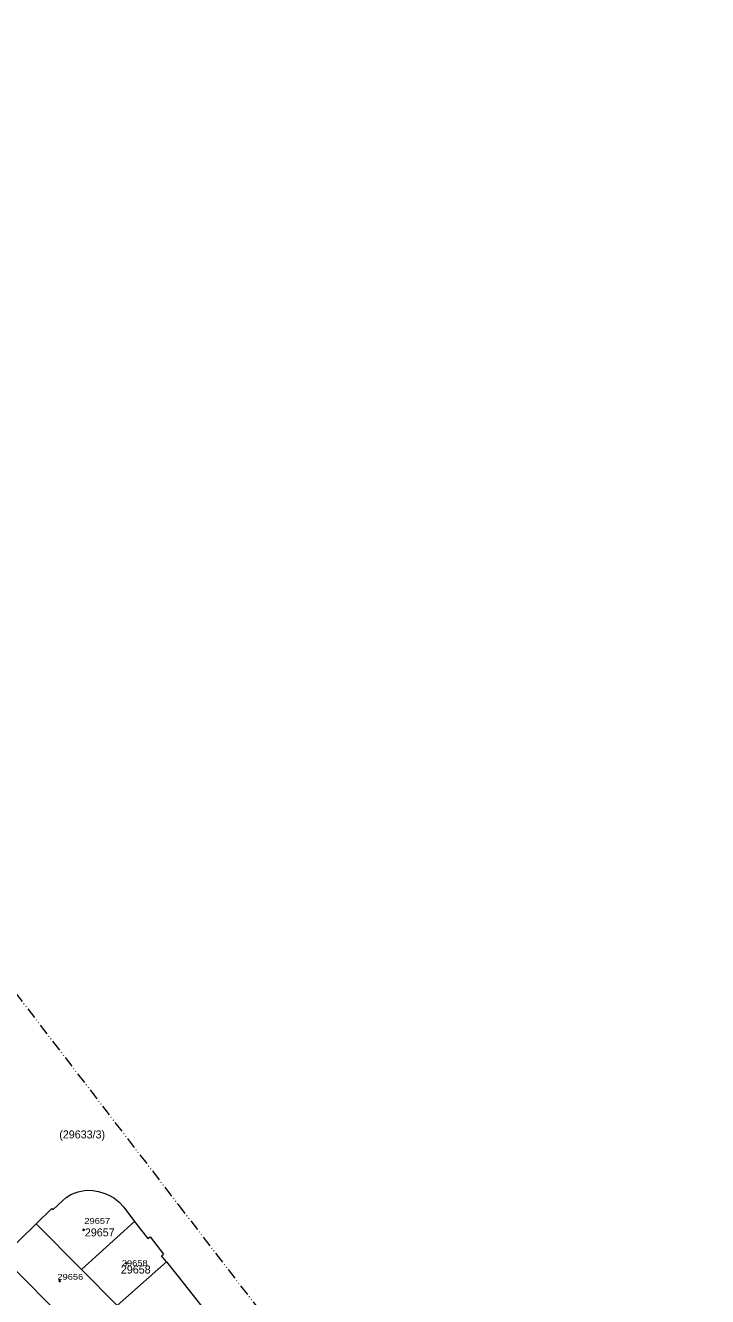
# Model space of a CAD drawing. Extents: x 650553 to 652508, y 239277 to 241647.
# Drawn here: x 652201 to 652508, y 241075 to 241647 of the extents above; entities that cross this region are included whole.
import ezdxf

# ---------------------------------------------------------------- set-up
doc = ezdxf.new("R2010")
doc.units = 0
doc.header["$PDMODE"] = 32
doc.header["$PDSIZE"] = 0.5
doc.linetypes.add('DASH_DOUBLE_DOT', pattern=[9.2, 5, -1.2, 0.3, -1.2, 0.3, -1.2])
for name, color, linetype in [('19', 7, 'Continuous'), ('20', 7, 'Continuous'), ('6', 7, 'Continuous')]:
    doc.layers.add(name, color=color, linetype=linetype)
for name, color, linetype, lineweight in [('3', 7, 'Continuous', 13), ('5', 7, 'Continuous', 13), ('52', 7, 'DASH_DOUBLE_DOT', 13)]:
    doc.layers.add(name, color=color, linetype=linetype, lineweight=lineweight)

msp = doc.modelspace()

# ---------------------------------------------------------------- linework, layer by layer
at = {"layer": '3'}
msp.add_line((652250.4, 241109), (652252.99, 241105.65), dxfattribs=at)
for points in [[(652206.29, 241107.91), (652213.3, 241114.88), (652213.82, 241114.32), (652218.01, 241118.23), (652219.66, 241119.75), (652221.78, 241121.1), (652223.8, 241121.94), (652225.1, 241122.4), (652227.01, 241122.86), (652229.04, 241123.07), (652231.77, 241123), (652234.26, 241122.48), (652237.09, 241121.63), (652239.23, 241120.64), (652241.21, 241119.63), (652243.41, 241117.78), (652245.58, 241115.4), (652250.4, 241109)], [(652150.66, 241053.06), (652170.97, 241073.05), (652191.12, 241093.11), (652206.29, 241107.91)], [(652252.99, 241105.65), (652256.45, 241101.33), (652257.46, 241102.1), (652263.54, 241094.35)], [(652264.91, 241090.8), (652262.66, 241093.6), (652263.54, 241094.35)], [(652264.91, 241090.8), (652270.04, 241084.31), (652274.57, 241078.57)], [(652274.57, 241078.57), (652284.02, 241066.57), (652263.96, 241048.58)]]:
    msp.add_lwpolyline(points, dxfattribs=at)
at = {"layer": '5'}
msp.add_line((652250.4, 241109), (652226.68, 241087.43), dxfattribs=at)
for points in [[(652206.29, 241107.91), (652226.68, 241087.43), (652242.7, 241071.24), (652247.71, 241065.85), (652263.96, 241048.58)], [(652191.12, 241093.11), (652191.613, 241092.61), (652221.38, 241062.42), (652200.98, 241042.45)], [(652227.01, 241056.59), (652230.87, 241060.14), (652242.7, 241071.24), (652264.91, 241090.8)]]:
    msp.add_lwpolyline(points, dxfattribs=at)
at = {"layer": '52'}
msp.add_lwpolyline([(651848.117, 241638.653), (651850.85, 241640.826), (651854.855, 241643.843), (651859.061, 241646.967), (651862.077, 241642.993), (651865.187, 241639.299), (651868.69, 241635.11), (651876.454, 241625.813), (651886.134, 241613.883), (651968.083, 241508.86), (652062.325, 241387.051), (652163.19, 241255.731), (652270.107, 241116.584), (652399.768, 240948.012), (652508.14, 240805.294)], dxfattribs=at)
at = {"layer": '6'}
for p in [(652227.607, 241105.25), (652246.888, 241090.12), (652216.817, 241082.25)]:
    msp.add_point(p, dxfattribs=at)

# ---------------------------------------------------------------- texts
at = {"layer": '19'}
for s, p in [('(29633/3)', (652216.621, 241146.357)), ('29657', (652228.131, 241102.292)), ('29658', (652244.33, 241085.589))]:
    msp.add_text(s, height=3.6, dxfattribs=at).set_placement(p)
at = {"layer": '20', "width": 1.2}
for s, p in [('29657', (652227.897, 241107.945)), ('29658', (652244.748, 241088.973)), ('29656', (652215.778, 241082.815))]:
    msp.add_text(s, height=2.6, dxfattribs=at).set_placement(p)

doc.saveas('drawing.dxf')
